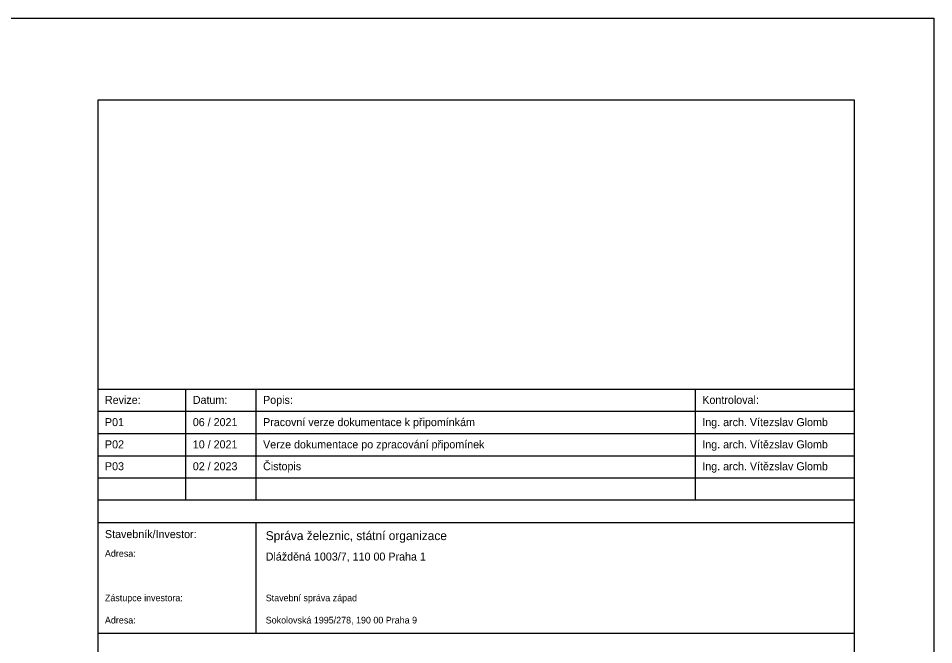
# Model space of a CAD drawing. Extents: x -823399 to -812899, y -1074543 to -1067118.
# Drawn here: x -818044 to -812899, y -1070640 to -1067118 of the extents above; entities that cross this region are included whole.
import ezdxf

# ---------------------------------------------------------------- set-up
doc = ezdxf.new("R2010")
doc.units = 0
doc.layers.add('formát', color=7, linetype='Continuous')
doc.layers.add('Popisove_pole', color=7, linetype='Continuous')

msp = doc.modelspace()

# ---------------------------------------------------------------- linework, layer by layer
at = {"layer": 'formát'}
msp.add_lwpolyline([(-818148.7, -1067117.7), (-812898.7, -1067117.7), (-812898.7, -1074542.7), (-818148.7, -1074542.7)], close=True, dxfattribs=at)
at = {"layer": 'Popisove_pole'}
for p, q in [((-817101.6, -1069827), (-817101.6, -1069202)), ((-816706.6, -1069827), (-816706.6, -1069202)), ((-814237.8, -1069827), (-814237.8, -1069202)), ((-817595.3, -1069327), (-813345.3, -1069327)), ((-817595.3, -1069452), (-813345.3, -1069452)), ((-817595.3, -1069577), (-813345.3, -1069577)), ((-817595.3, -1069702), (-813345.3, -1069702)), ((-816706.6, -1070577), (-816706.6, -1069952))]:
    msp.add_line(p, q, dxfattribs=at)
for points in [[(-817595.3, -1067577), (-813345.3, -1067577), (-813345.3, -1074077), (-817595.3, -1074077)], [(-817595.3, -1069202), (-813345.3, -1069202), (-813345.3, -1069827), (-817595.3, -1069827)], [(-817595.3, -1069952), (-813345.3, -1069952), (-813345.3, -1070577), (-817595.3, -1070577)]]:
    msp.add_lwpolyline(points, close=True, dxfattribs=at)

# ---------------------------------------------------------------- texts
for s, height, p in [('Revize:', 45, (-817556.7, -1069285.7)), ('Datum:', 45, (-817062.9, -1069285.7)), ('Popis:', 45, (-816667.9, -1069285.7)), ('Kontroloval:', 45, (-814199.2, -1069285.7)), ('P01', 45, (-817556.7, -1069410.7)), ('06 / 2021', 45, (-817062.9, -1069410.7)), ('Pracovní verze dokumentace k připomínkám', 45, (-816667.9, -1069410.7)), ('Ing. arch. Vítezslav Glomb', 45, (-814199.2, -1069410.7)), ('P02', 45, (-817556.7, -1069535.7)), ('10 / 2021', 45, (-817062.9, -1069535.7)), ('Verze dokumentace po zpracování připomínek', 45, (-816667.9, -1069535.7)), ('Ing. arch. Vítězslav Glomb', 45, (-814199.2, -1069535.7)), ('P03', 45, (-817556.7, -1069658.7)), ('02 / 2023', 45, (-817062.9, -1069658.7)), ('Čistopis', 45, (-816667.9, -1069658.7)), ('Ing. arch. Vítězslav Glomb', 45, (-814199.2, -1069658.7)), ('Stavebník/Investor:', 45, (-817556.7, -1070040.2)), ('Správa železnic, státní organizace', 50, (-816652.9, -1070051.5)), ('Adresa:', 37.5, (-817556.7, -1070145.2)), ('Dlážděná 1003/7, 110 00 Praha 1', 45, (-816652.9, -1070166.5)), ('Zástupce investora:', 37.5, (-817556.7, -1070395.2)), ('Stavební správa západ', 37.5, (-816652.9, -1070395.2)), ('Adresa:', 37.5, (-817556.7, -1070520.2)), ('Sokolovská 1995/278, 190 00 Praha 9', 37.5, (-816652.9, -1070520.2))]:
    msp.add_text(s, height=height, rotation=360, dxfattribs=at).set_placement(p)

doc.saveas('drawing.dxf')
